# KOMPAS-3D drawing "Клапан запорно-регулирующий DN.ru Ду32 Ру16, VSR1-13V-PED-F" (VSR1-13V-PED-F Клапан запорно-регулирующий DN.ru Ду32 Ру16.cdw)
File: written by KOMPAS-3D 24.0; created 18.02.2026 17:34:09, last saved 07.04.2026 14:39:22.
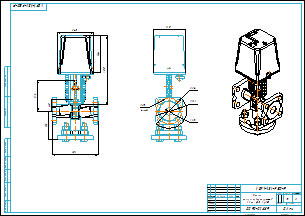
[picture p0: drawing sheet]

Document properties: Автор: R2D2; Форматы листов документа: A2; Полное имя файла: VSR1-13V-PED-F Клапан запорно-регулирующий DN.ru Ду32 Ру16.m3d; Масса: 9.2; Наименование: Клапан запорно-регулирующий DN.ru Ду32 Ру16; Количество листов документа: 1; Примечание: D090-02889

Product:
- Part/product: Клапан запорно-регулирующий DN.ru Ду32 Ру16  | designation VSR1-13V-PED-F
    Масса: 9.2
    Раздел спецификации: Прочие изделия
    Примечание: D090-02889

Views: Вид 1, Спереди
Referenced files in E:\Работа\Зайцев\Солянка\VSR1-13V-PED-F Клапан запорно-регулирующий DN.ru\DN15\DN15 Kv0.16\: VSR1-13V-PED-F Клапан запорно-регулирующий DN.ru Ду15 Ру16.m3d
Referenced files in E:\Работа\Зайцев\Солянка\VSR1-13V-PED-F Клапан запорно-регулирующий DN.ru\DN32\: VSR1-13V-PED-F Клапан запорно-регулирующий DN.ru Ду32 Ру16.m3d
Referenced files in E:\Работа\Зайцев\Для компаса\: чертеж DN.ru А3.cdt
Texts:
  Линейный размер
  VSR1-13V-PED-F
  чертеж DN.ru А3.cdt
  Клапан
  запорно-регулирующий
  DN.ru Ду32 Ру16
  Клапан запорно-регулирующий DN.ru Ду32 Ру16
  VSR1-13V-PED-F Клапан запорно-регулирующий DN.ru Ду32 Ру16
Dimensions and other numbers on the sheet: 0; 3; 2; 4; 180; 143; 45; 120; 110; 144; 269; 1:2; 1; 9,2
